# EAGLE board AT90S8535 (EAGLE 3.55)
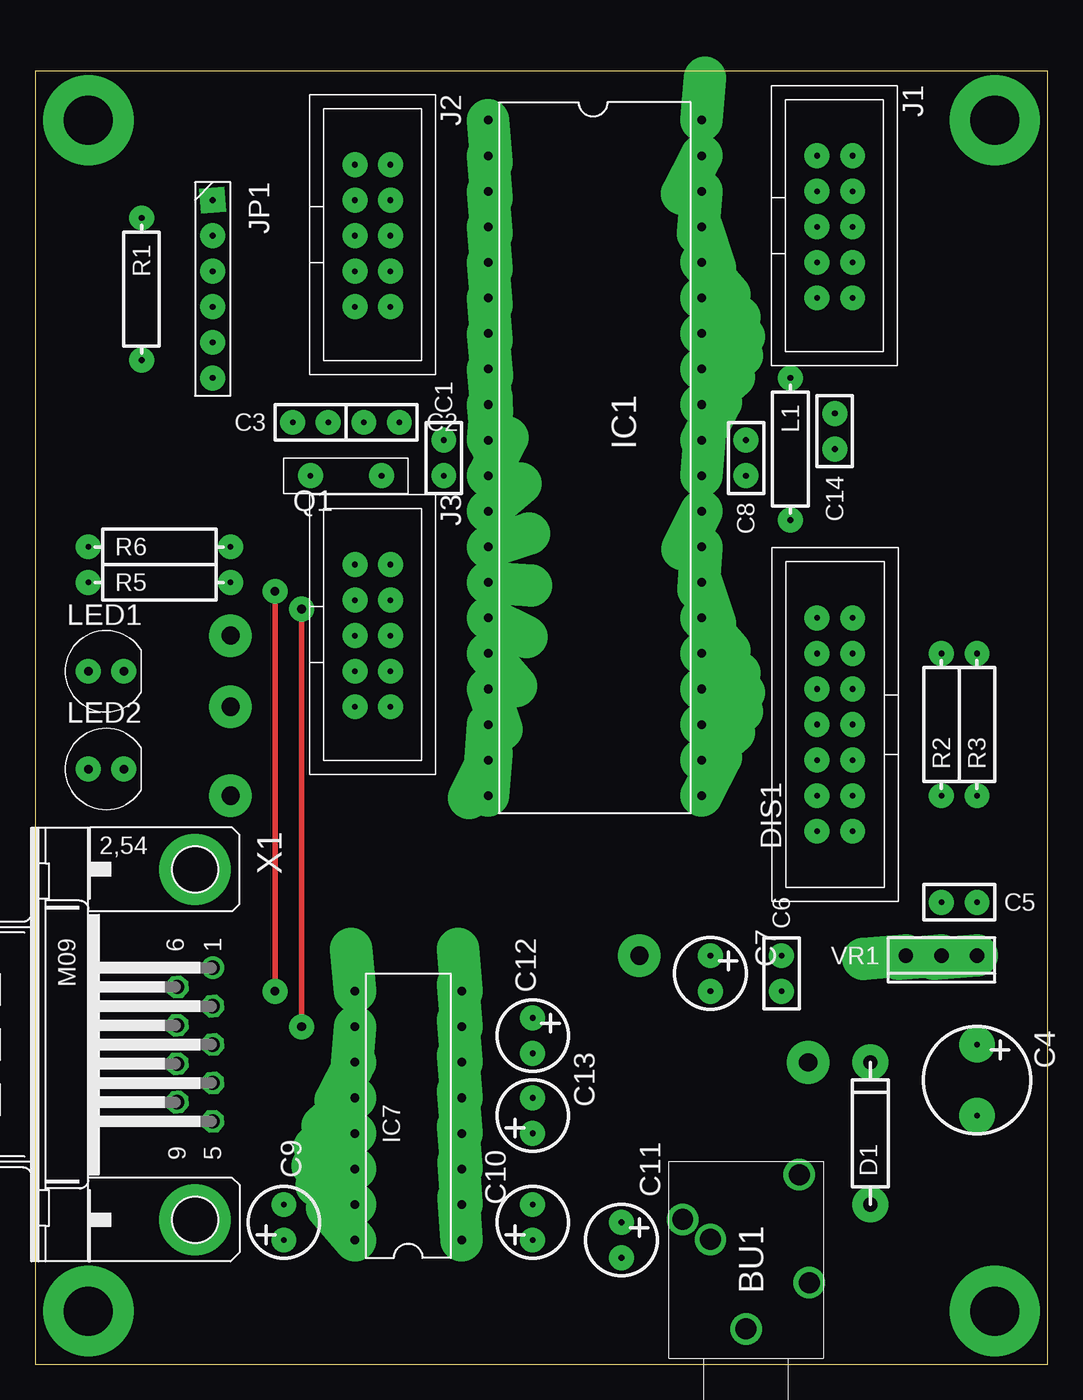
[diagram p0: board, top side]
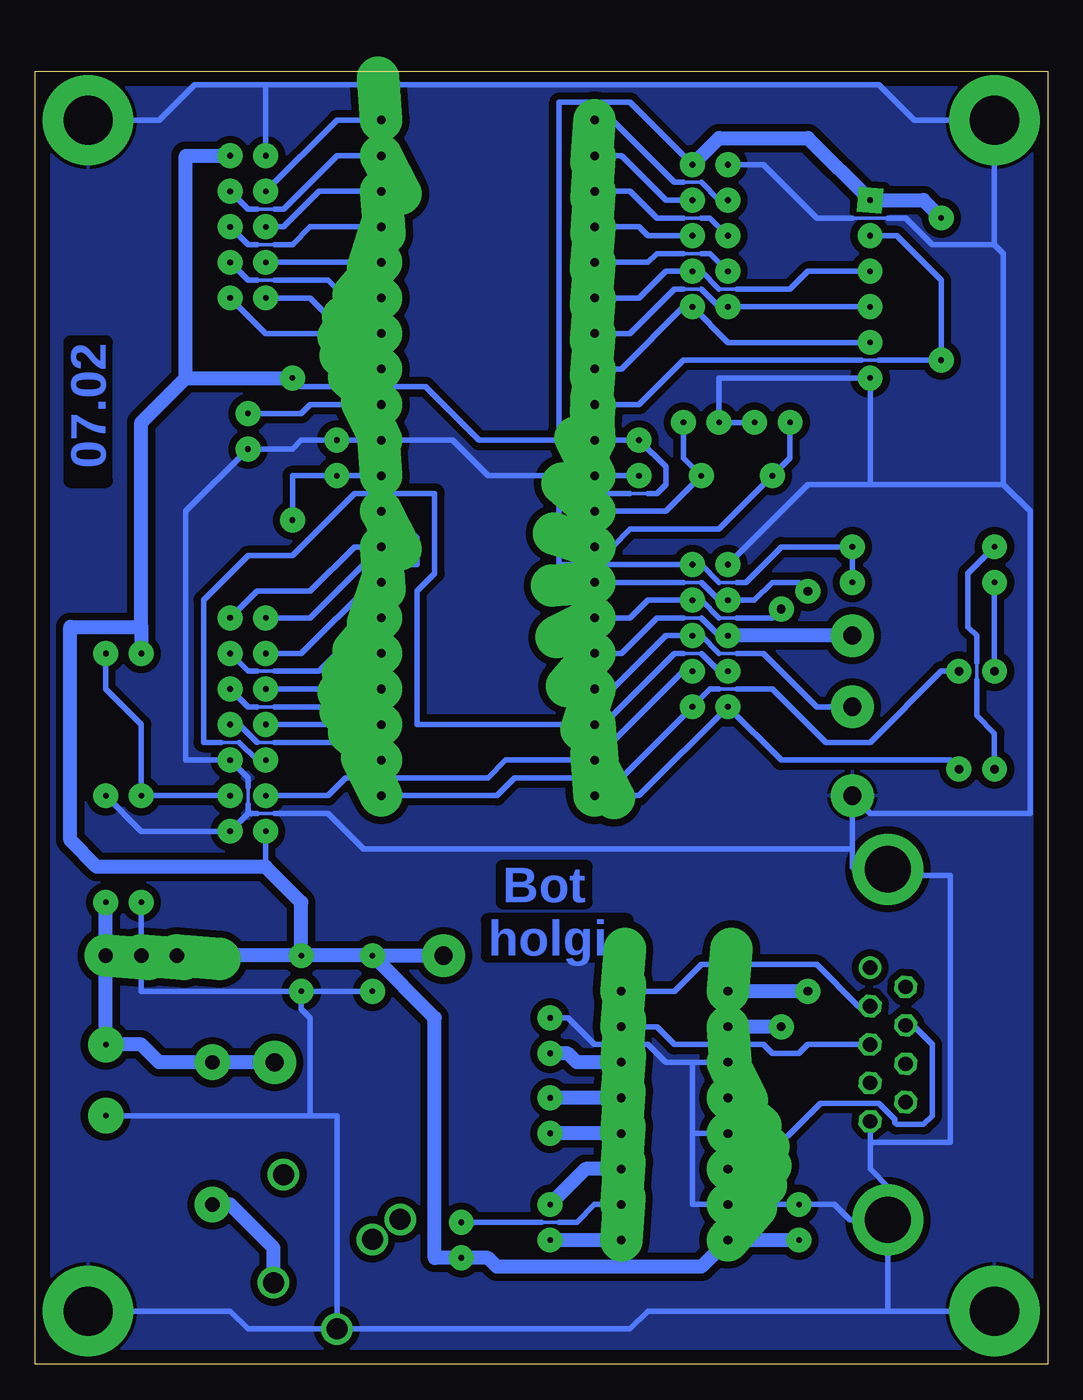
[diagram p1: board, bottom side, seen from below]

Size 72.37 x 92.38 mm. Coordinates in mm from the lower left corner, seen from the top.
Outline: 0,0 72.37,0 72.37,92.38 0,92.38 0,0
Copper layers used: Top, Bottom

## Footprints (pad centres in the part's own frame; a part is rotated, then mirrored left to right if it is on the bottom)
_3,5MM = drill 1.499 pad 2.184 round:  0,0;  3.302,-4.521;  7.823,4.521;  6.401,2.54;  11.024,-3.81
RM2,5 = drill 0.406 pad 1.778 round:  -1.27,0;  1.27,0
KO02 = drill 0.406 pad 2.54 round:  -2.54,0;  2.54,0
KO01 = drill 0.406 pad 1.778 round:  -1.27,0;  1.27,0
O_1A = drill 1.016 pad 2.54 round:  -5.08,0;  5.08,0
7 = drill 0.406 pad 1.778 round:  0,0;  2.54,0;  5.08,0;  7.62,0;  10.16,0;  10.16,2.54;  7.62,2.54;  5.08,2.54;  2.54,2.54;  0,2.54;  12.7,0;  12.7,2.54;  15.24,0;  15.24,2.54
L-40B = drill 0.61 pad 3.048 offset:  -24.13,-7.62;  -21.59,-7.62;  -8.89,-7.62;  -6.35,-7.62;  -19.05,-7.62;  -16.51,-7.62;  -11.43,-7.62;  -13.97,-7.62;  -3.81,-7.62;  -1.27,-7.62;  1.27,-7.62;  3.81,-7.62;  6.35,-7.62;  8.89,-7.62;  11.43,-7.62;  13.97,-7.62;  16.51,-7.62;  19.05,-7.62;  21.59,-7.62;  24.13,-7.62;  24.13,7.62;  21.59,7.62;  19.05,7.62;  16.51,7.62;  13.97,7.62;  11.43,7.62;  8.89,7.62;  6.35,7.62;  3.81,7.62;  1.27,7.62;  -1.27,7.62;  -3.81,7.62;  -6.35,7.62;  -8.89,7.62;  -11.43,7.62;  -13.97,7.62;  -16.51,7.62;  -19.05,7.62;  -21.59,7.62;  -24.13,7.62
L-16B = drill 0.61 pad 3.048 offset:  -8.89,-3.81;  -6.35,-3.81;  6.35,-3.81;  8.89,-3.81;  -3.81,-3.81;  -1.27,-3.81;  3.81,-3.81;  1.27,-3.81;  8.89,3.81;  6.35,3.81;  3.81,3.81;  1.27,3.81;  -1.27,3.81;  -3.81,3.81;  -6.35,3.81;  -8.89,3.81
5 = drill 0.406 pad 1.778 round:  0,0;  2.54,0;  5.08,0;  7.62,0;  10.16,0;  10.16,2.54;  7.62,2.54;  5.08,2.54;  2.54,2.54;  0,2.54
6 = drill 0.406 pad 1.778 square:  0,0 | drill 0.406 pad 1.778 round:  5.08,0;  10.16,0;  12.7,0;  7.62,0;  2.54,0
S04 = drill 0.406 pad 1.778 round:  -5.08,0;  5.08,0
D_5MM = drill 0.61 pad 1.778 round:  -1.27,0;  1.27,0
GEL = drill 1.295 pad 3.048 round:  0,0
ARZ_ST = drill 0.406 pad 1.778 round:  -2.54,0;  2.54,0
HRUNG = drill 3.505 pad 6.452 round:  0,0
220A = drill 1.016 pad 3.048 offset:  -2.54,0;  0,0;  2.54,0
9HP = drill 1.016 pad 1.6 octagon:  5.486,1.27;  2.743,1.27;  0,1.27;  -2.743,1.27;  4.115,-1.27;  1.372,-1.27;  -1.372,-1.27;  -4.115,-1.27 | drill 1.016 pad 1.6 round:  -5.486,1.27 | drill 3.302 pad 5.08 round:  -12.522,0;  12.522,0

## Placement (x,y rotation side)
BU1  BU_3,5MM  [_3,5MM]  50.8,2.54 90 top
C1  C100NK  [RM2,5]  29.21,64.77 90 top
C2  22p  [RM2,5]  24.77,67.31 0 top
C3  22p  [RM2,5]  19.68,67.31 180 top
C4  470u/25  [KO02]  67.31,20.32 270 top
C5  C100NK  [RM2,5]  66.04,33.02 0 top
C6  C100NK  [RM2,5]  53.34,27.94 90 top
C7  100u  [KO01]  48.26,27.94 270 top
C8  C100NK  [RM2,5]  50.8,64.77 270 top
C9  10u  [KO01]  17.78,10.16 90 top
C10  10u  [KO01]  35.56,10.16 90 top
C11  10u  [KO01]  41.91,8.89 270 top
C12  10u  [KO01]  35.56,23.5 270 top
C13  10u  [KO01]  35.56,17.78 90 top
C14  C100NK  [RM2,5]  57.15,66.67 270 top
D1  1N4001  [O_1A]  59.69,16.51 90 top
DIS1  LCD1  [7]  58.42,38.1 90 top
IC1  90S8535-P  [L-40B]  40.01,64.77 270 top
IC7  MAX232  [L-16B]  26.67,17.78 90 top
J1  8BITPORT  [5]  55.88,86.36 270 top
J2  8BITPORT  [5]  22.86,85.72 270 top
J3  8BITPORT  [5]  22.86,57.15 270 top
JP1  PINHD-1X6  [6]  12.7,83.19 270 top
L1  100uH  [S04]  53.98,65.41 270 top
LED1  rot  [D_5MM]  5.08,49.53 0 top
LED2  grn  [D_5MM]  5.08,42.55 0 top
N1  Int1  [GEL]  13.97,46.99 0 top
N2  Int0  [GEL]  13.97,52.07 0 top
N3  gnd  [GEL]  13.97,40.64 0 top
N4  +5V  [GEL]  43.18,29.21 0 top
N5  +Ub  [GEL]  55.24,21.59 0 top
Q1  8MHz  [ARZ_ST]  22.23,63.5 0 top
R1  100k  [S04]  7.62,76.83 270 top
R2  12k  [S04]  64.77,45.72 90 top
R3  1k  [S04]  67.31,45.72 90 top
R5  1k  [S04]  8.89,55.88 0 top
R6  1k  [S04]  8.89,58.42 0 top
U$30  BOHRUNG  [HRUNG]  3.81,88.9 0 top
U$31  BOHRUNG  [HRUNG]  68.58,88.9 0 top
U$32  BOHRUNG  [HRUNG]  68.58,3.81 0 top
U$33  BOHRUNG  [HRUNG]  3.81,3.81 0 top
VR1  7805  [220A]  64.77,29.21 180 top
X1  M09HP  [9HP]  11.43,22.86 270 top

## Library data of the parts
BU1 = bts
C1-C14 D1 DIS1 IC1 IC7 J1-J3 JP1 L1 LED1 LED2 Q1 R1-R3 R5 R6 VR1 = holg_plt
N1-N5 U$30-U$33 = holgnorm
X1 = subd-a

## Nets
+5V: C1. C6. C7. C9. C11. DIS1. IC1. IC7. J1. J2. J3. JP1. L1. N4. R1. R2. R5. R6. VR1.
GND: BU1. C1. C2. C3. C4. C5. C6. C7. C8. C9. C12. C14. DIS1. IC1. IC7. J1. J2. J3. JP1. N3. R3. U$30. U$31. U$32. U$33. VR1. X1.
INT0: IC1. J3. N2.
INT1: IC1. J3. N1.
LCD_CS: DIS1. IC1. J3.
LCD_RS: DIS1. IC1. J3.
MISO: IC1. J2. JP1.
MOSI: IC1. J2. JP1.
N$1: DIS1. IC1.
N$2: DIS1. IC1.
N$3: DIS1. IC1.
N$4: DIS1. IC1.
N$5: DIS1. IC1.
N$6: C3. IC1. Q1.
N$7: DIS1. IC1.
N$8: C2. IC1. Q1.
N$9: C12. IC7.
N$10: C11. IC7.
N$11: DIS1. IC1.
N$12: C10. IC7.
N$13: C13. IC7.
N$14: IC1. J1.
N$15: C10. IC7.
N$16: DIS1. IC1.
N$17: C13. IC7.
N$18: IC1. J1.
N$19: IC1. J1.
N$20: DIS1. R2. R3.
N$21: IC1. J1.
N$22: IC1. J1.
N$23: IC1. J1.
N$24: C8. IC1. L1.
N$25: IC1. J1.
N$26: IC1. J1.
N$27: C14. IC1.
N$29: IC1. J3. LED1.
N$30: IC1. J2.
N$31: IC1. J2.
N$32: IC1. J2.
N$33: IC1. J2.
N$34: IC1. J2.
N$35: IC1. J3. LED2.
N$36: LED1. R5.
N$37: LED2. R6.
N$42: C4. C5. D1. N5. VR1.
N$50: BU1. D1.
RESET: IC1. JP1. R1.
RTS_OUT: IC7. X1.
RXD: IC1. IC7. J3.
RXD_IN: IC7. X1.
SCK: IC1. J2. JP1.
TXD: IC1. IC7. J3.
TXD_OUT: IC7. X1.

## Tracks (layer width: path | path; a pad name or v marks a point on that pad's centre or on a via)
+5V
  Bottom 0.254: 23.5,55.88 22.23,55.88 | 28.57,62.23 29.84,62.23
  Bottom 0.406: 55.88,35.56 55.88,38.1 | 34.92,66.04 32.38,66.04 C1. 27.3,64.14 27.3,62.87 27.94,62.23 28.57,62.23 | 53.98,70.48 53.34,69.85 44.45,69.85 40.64,66.04 34.92,66.04 | R5. R6. 19.05,58.42 21.59,55.88 22.23,55.88 | 23.5,55.88 24.77,57.15 J3. 34.92,57.15 34.92,62.23 29.84,62.23 | J2. 29.84,90.17 34.92,90.17 34.92,66.04
  Bottom 1.016: 17.78,8.89 IC7. 24.77,6.99 39.37,6.99 40.01,7.62 C11. 43.81,7.62 43.81,24.77 48.26,29.21 | C6. VR1. | 48.26,29.21 C6. | 7.62,81.92 8.89,83.19 12.7,83.19 17.14,87.63 23.5,87.63 J2. | C6. 53.34,33.02 55.88,35.56 67.94,35.56 69.85,37.47 69.85,52.7 64.77,52.7 | 64.77,52.7 R2. | 48.26,29.21 N4. | J1. 61.59,86.36 61.59,70.48 | 64.77,52.7 64.77,67.31 61.59,70.48 | 61.59,70.48 53.98,70.48
GND
  Bottom 0.254: 11.43,81.92 13.97,81.92 | 57.15,40.01 57.15,41.27 | 55.24,39.37 56.52,39.37
  Bottom 0.406: X1. 11.43,12.7 12.7,13.97 12.7,15.88 | 12.7,15.88 12.7,17.37 | 12.7,15.88 6.99,15.88 6.99,34.92 8.89,34.92 9.35,35.38 11.43,35.38 13.79,35.38 13.97,35.56 13.97,36.83 | X1. 14.15,10.34 15.24,11.43 C9. 22.86,11.43 25.4,11.43 25.4,16.51 | 25.4,16.51 22.86,16.51 | 25.4,16.51 25.4,21.59 | 25.4,21.59 22.86,21.59 | 25.4,21.59 27.3,21.59 28.57,22.86 32.38,22.86 34.29,24.77 35.56,24.77 | 11.43,3.81 X1. | U$33. 11.43,3.81 | 50.8,2.54 29.84,2.54 28.57,3.81 11.43,3.81 | 67.31,40.64 64.77,38.1 58.42,38.1 57.15,39.37 | 64.77,33.02 64.77,29.21 64.77,26.67 53.34,26.67 | 53.34,26.67 C7. | U$32. 58.42,3.81 57.15,2.54 50.8,2.54 | 52.7,17.78 50.8,17.78 50.8,2.54 | 52.7,17.78 C4. | 52.7,17.78 52.7,24.77 53.34,25.4 53.34,26.67 | 22.86,85.72 20.32,85.72 16.51,81.92 13.97,81.92 | 3.17,62.87 1.27,60.96 1.27,39.37 12.7,39.37 N3. 13.97,36.83 | 55.88,91.44 12.06,91.44 9.53,88.9 U$30. 3.81,80.01 | 55.88,91.44 60.96,91.44 63.5,88.9 U$31. | 11.43,81.92 10.16,81.92 8.26,80.01 3.81,80.01 | 29.21,63.5 32.38,63.5 40.01,63.5 42.55,66.04 47.62,66.04 50.8,66.04 53.34,66.04 53.98,65.41 C14. 61.59,60.96 61.59,43.18 58.42,43.18 57.15,41.91 57.15,41.27 | 55.88,91.44 55.88,86.36 | 3.81,80.01 3.17,79.38 3.17,62.87 | 57.15,39.37 57.15,40.01 | 3.17,62.87 12.7,62.87 | 20.95,67.31 23.5,67.31 23.5,70.48 12.7,70.48 12.7,62.87 | 22.86,57.15 17.14,62.87 12.7,62.87 | 56.52,39.37 57.15,39.37 | 55.24,39.37 51.44,39.37 48.9,36.83 13.97,36.83
  pour Bottom (isolate 0.508): 0.64,91.44 0.64,0.64 71.75,0.64 71.75,91.44
INT0
  Bottom 0.254: 24.77,53.34 26.04,53.34
  Bottom 0.406: 22.86,52.07 23.5,52.07 24.77,53.34 | 32.38,50.8 30.48,50.8 27.94,53.34 26.04,53.34
  Bottom 1.016: N2. 22.86,52.07
INT1
  Bottom 0.254: 22.23,50.8 23.5,50.8
  Bottom 0.406: 23.5,50.8 24.77,52.07 25.4,52.07 27.3,52.07 31.11,48.26 32.38,48.26 | N1. 16.51,46.99 20.32,50.8 22.23,50.8
LCD_CS
  Bottom 0.254: 24.77,50.8 26.04,50.8 | 59.05,44.45 57.78,44.45
  Bottom 0.406: 22.86,49.53 23.5,49.53 24.77,50.8 | 26.04,50.8 26.67,50.8 31.75,45.72 32.38,45.72 45.09,45.72 45.09,55.24 43.81,56.52 43.81,62.23 49.53,62.23 53.98,57.78 57.15,57.78 60.33,54.61 60.33,44.45 59.05,44.45 | 55.88,43.18 56.52,43.18 57.78,44.45
LCD_RS
  Bottom 0.406: 25.4,49.53 26.04,49.53 32.38,43.18 38.73,43.18 40.01,41.91 50.16,41.91 51.44,40.64 55.88,40.64
MISO
  Bottom 0.254: 24.77,76.83 26.04,76.83
  Bottom 0.406: 12.7,75.56 22.86,75.56 23.5,75.56 24.77,76.83 | 32.38,73.66 29.84,73.66 26.67,76.83 26.04,76.83
MOSI
  Bottom 0.254: 22.23,76.83 23.5,76.83
  Bottom 0.406: 23.5,76.83 24.77,78.11 25.4,78.11 27.3,78.11 29.21,76.2 32.38,76.2 | 12.7,78.11 17.14,78.11 18.41,76.83 22.23,76.83
N$1
  Bottom 0.254: 55.24,44.45 56.52,44.45
  Bottom 0.406: 47.62,43.18 49.53,43.18 50.8,44.45 55.24,44.45 | 58.42,45.72 57.78,45.72 56.52,44.45
N$2
  Bottom 0.406: 47.62,45.72 55.88,45.72
N$3
  Bottom 0.254: 55.24,46.99 56.52,46.99
  Bottom 0.406: 47.62,48.26 48.9,48.26 50.16,46.99 55.24,46.99 | 58.42,48.26 57.15,46.99 56.52,46.99
N$4
  Bottom 0.406: 47.62,50.8 48.9,50.8 51.44,48.26 55.88,48.26
N$5
  Bottom 0.254: 55.24,49.53 56.52,49.53
  Bottom 0.406: 47.62,53.34 48.26,53.34 52.07,49.53 55.24,49.53 | 58.42,50.8 57.15,49.53 56.52,49.53
N$6
  Bottom 0.406: 32.38,58.42 31.11,58.42 29.84,59.69 23.5,59.69 19.68,63.5 18.41,64.77 C3.
N$7
  Bottom 0.406: 47.62,55.88 48.26,55.88 53.34,50.8 55.88,50.8
N$8
  Bottom 0.406: 32.38,60.96 27.3,60.96 Q1. 26.04,64.77 C2.
N$9
  Bottom 1.016: 30.48,21.59 33.66,21.59 34.29,22.23 C12.
N$10
  Bottom 0.254: 34.92,10.16 36.2,10.16
  Bottom 0.406: 30.48,11.43 32.38,11.43 33.66,10.16 34.92,10.16 | 36.2,10.16 41.91,10.16
N$11
  Bottom 0.406: 47.62,58.42 49.53,58.42 52.7,55.24 56.52,55.24 58.42,53.34
N$12
  Bottom 1.016: 30.48,13.97 33.02,13.97 C10.
N$13
  Bottom 1.016: 30.48,19.05 C13.
N$14
  Bottom 0.406: IC1. 50.8,88.9 55.88,83.82
N$15
  Bottom 1.016: 30.48,8.89 35.56,8.89
N$16
  Bottom 0.406: 47.62,60.96 46.99,60.96 45.09,59.05 45.09,57.15 48.9,57.15 52.7,53.34 DIS1.
N$17
  Bottom 1.016: 30.48,16.51 35.56,16.51
N$18
  Bottom 0.254: 55.24,82.55 56.52,82.55
  Bottom 0.406: 47.62,86.36 50.8,86.36 54.61,82.55 55.24,82.55 | 58.42,83.82 57.15,82.55 56.52,82.55
N$19
  Bottom 0.406: 47.62,83.82 52.07,83.82 54.61,81.28 55.88,81.28
N$20
  Bottom 0.406: 58.42,40.64 64.77,40.64 64.77,45.72 67.31,48.26 R3.
N$21
  Bottom 0.254: 55.24,80.01 56.52,80.01
  Bottom 0.406: 47.62,81.28 52.7,81.28 53.98,80.01 55.24,80.01 | 58.42,81.28 57.15,80.01 56.52,80.01
N$22
  Bottom 0.406: 47.62,78.74 55.88,78.74
N$23
  Bottom 0.254: 55.24,77.47 56.52,77.47
  Bottom 0.406: 47.62,76.2 50.16,76.2 51.44,77.47 55.24,77.47 | 58.42,78.74 57.15,77.47 56.52,77.47
N$24
  Bottom 0.406: 47.62,63.5 C8. 53.98,63.5 L1.
N$25
  Bottom 0.406: 47.62,73.66 50.16,73.66 52.7,76.2 55.88,76.2
N$26
  Bottom 0.406: 47.62,71.12 49.53,71.12 52.07,73.66 55.88,73.66 58.42,76.2
N$27
  Bottom 0.406: 47.62,68.58 52.7,68.58 53.34,67.94 57.15,67.94
N$29
  Bottom 0.254: 22.23,48.26 23.5,48.26
  Bottom 0.406: 23.5,48.26 24.13,48.26 25.4,46.99 30.48,41.91 38.1,41.91 39.37,40.64 47.62,40.64 | LED1. 7.62,49.53 12.7,44.45 15.88,44.45 19.68,48.26 22.23,48.26
N$30
  Bottom 0.254: 24.77,79.38 26.04,79.38
  Bottom 0.406: 22.86,78.11 24.13,79.38 24.77,79.38 | 32.38,78.74 28.57,78.74 27.94,79.38 26.04,79.38
N$31
  Bottom 0.406: 25.4,80.64 28.57,80.64 29.21,81.28 32.38,81.28
N$32
  Bottom 0.254: 24.77,81.92 26.04,81.92
  Bottom 0.406: 22.86,80.64 24.13,81.92 24.77,81.92 | 32.38,83.82 29.84,83.82 27.94,81.92 26.04,81.92
N$33
  Bottom 0.406: 25.4,83.19 27.3,83.19 30.48,86.36 32.38,86.36
N$34
  Bottom 0.254: 24.77,84.45 26.04,84.45
  Bottom 0.406: 22.86,83.19 23.5,83.19 24.77,84.45 | 32.38,88.9 31.11,88.9 26.67,84.45 26.04,84.45
N$35
  Bottom 0.406: LED2. 6.99,43.18 19.05,43.18 22.86,46.99 29.21,40.64 32.38,40.64
N$36
  Bottom 0.406: 3.81,49.53 3.81,55.88
N$37
  Bottom 0.254: 5.08,48.9 5.08,50.16
  Bottom 0.406: 3.81,58.42 5.71,56.52 5.71,52.7 5.08,52.07 5.08,50.16 | 3.81,42.55 3.81,45.09 5.08,46.35 5.08,48.9
N$42
  Bottom 1.016: C5. 67.31,29.21 67.31,22.86 64.77,22.86 63.5,21.59 D1. N5.
N$50
  Bottom 1.016: 55.32,5.84 55.32,8.33 58.42,11.43 59.69,11.43
RESET
  Bottom 0.254: 12.06,71.75 13.34,71.75
  Bottom 0.406: JP1. 10.79,80.64 7.62,77.47 R1. 12.06,71.75 | 32.38,68.58 29.21,68.58 26.04,71.75 13.34,71.75
RTS_OUT
  Bottom 0.406: 10.16,24.23 9.63,24.23 8.26,22.86 8.26,17.78 8.89,17.14 10.79,17.14 10.92,17.27 10.92,17.53 12.06,18.67 16.26,18.67 20.95,13.97 22.86,13.97
RXD  (via drill 0.61 pad 1.78)
  Top 0.406: v17.14,26.67 v17.14,55.24
  Bottom 0.254: 24.77,55.88 26.04,55.88
  Bottom 0.406: v17.14,55.24 17.78,55.88 19.68,55.88 20.95,54.61 22.86,54.61 23.5,54.61 24.77,55.88 | 26.04,55.88 32.38,55.88
  Bottom 1.016: v17.14,26.67 22.86,26.67
RXD_IN
  Bottom 0.406: 12.7,25.6 13.54,25.6 16.51,28.57 24.77,28.57 26.67,26.67 30.48,26.67
SCK
  Bottom 0.406: 12.7,73.03 22.86,73.03 25.4,75.56 26.04,75.56 30.48,71.12 32.38,71.12
TXD  (via drill 0.61 pad 1.78)
  Top 0.406: v19.05,24.13 v19.05,53.98
  Bottom 0.254: 22.23,53.34 23.5,53.34
  Bottom 0.406: 23.5,53.34 24.77,54.61 25.4,54.61 28.57,54.61 29.84,53.34 32.38,53.34 | v19.05,53.98 19.68,53.34 22.23,53.34
  Bottom 1.016: v19.05,24.13 22.86,24.13
TXD_OUT
  Bottom 0.406: 30.48,24.13 27.94,24.13 26.67,22.86 20.32,22.86 19.68,22.23 17.78,22.23 17.14,22.86 12.7,22.86

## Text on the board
Bottom: 07.02 | Bot | holgi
